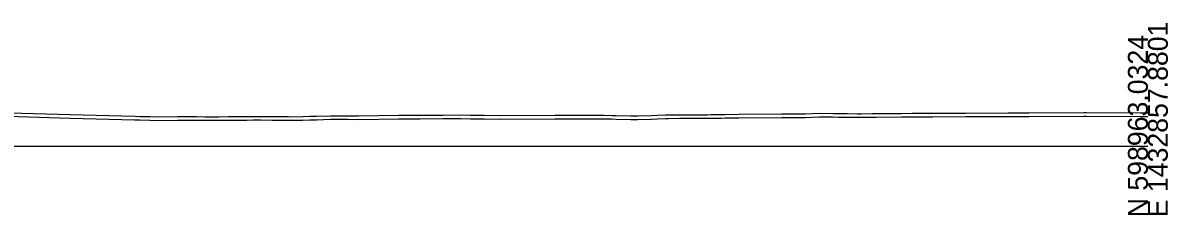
# Model space of a CAD drawing. Extents: x -26 to 2203, y -10 to 12201.
# Drawn here: x 442.1 to 602.8, y 9490.3 to 9517.3 of the extents above; entities that cross this region are included whole.
import ezdxf

# ---------------------------------------------------------------- set-up
doc = ezdxf.new("R2010")
doc.units = 0
for name, color, linetype in [('DESIGN - SHEET - Light Grid', 7, 'Continuous'), ('SURVEY - GROUND - Bottom of Topsoil Layer', 7, 'Continuous'), ('SURVEY - GROUND - Top of Ground', 7, 'Continuous')]:
    doc.layers.add(name, color=color, linetype=linetype)

msp = doc.modelspace()

# ---------------------------------------------------------------- linework, layer by layer
at = {"layer": 'DESIGN - SHEET - Light Grid'}
msp.add_line((300, 9500), (600, 9500), dxfattribs=at)
at = {"layer": 'SURVEY - GROUND - Bottom of Topsoil Layer'}
for p, q in [((436.02, 9504.31), (448.73, 9503.94)), ((448.73, 9503.94), (457.81, 9503.69)), ((457.81, 9503.69), (458.48, 9503.67)), ((458.48, 9503.67), (459.88, 9503.64)), ((459.88, 9503.64), (461.13, 9503.61)), ((461.13, 9503.61), (463.78, 9503.66)), ((463.78, 9503.66), (465.65, 9503.65)), ((465.65, 9503.65), (466.43, 9503.65)), ((466.43, 9503.65), (467.61, 9503.63)), ((467.61, 9503.63), (469.08, 9503.63)), ((469.08, 9503.63), (469.57, 9503.63)), ((469.57, 9503.63), (470.96, 9503.64)), ((470.96, 9503.64), (471.73, 9503.64)), ((471.73, 9503.64), (473.49, 9503.65)), ((473.49, 9503.65), (474.39, 9503.67)), ((474.39, 9503.67), (475.45, 9503.67)), ((475.45, 9503.67), (477.04, 9503.65)), ((477.04, 9503.65), (477.41, 9503.65)), ((477.41, 9503.65), (478.49, 9503.64)), ((478.49, 9503.64), (479.37, 9503.64)), ((479.37, 9503.64), (479.69, 9503.63)), ((479.69, 9503.63), (481.34, 9503.66)), ((481.34, 9503.66), (482.34, 9503.7)), ((482.34, 9503.7), (483.3, 9503.71)), ((483.3, 9503.71), (485.26, 9503.76)), ((485.26, 9503.76), (486.02, 9503.77)), ((486.02, 9503.77), (487.22, 9503.76)), ((487.22, 9503.76), (487.64, 9503.77)), ((487.64, 9503.77), (489.18, 9503.75)), ((489.18, 9503.75), (494.86, 9503.84)), ((494.86, 9503.84), (495.59, 9503.83)), ((495.59, 9503.83), (496.17, 9503.83)), ((496.17, 9503.83), (497.85, 9503.82)), ((497.85, 9503.82), (501.07, 9503.86)), ((501.07, 9503.86), (503.54, 9503.87)), ((503.54, 9503.87), (504.89, 9503.85)), ((504.89, 9503.85), (506.19, 9503.83)), ((506.19, 9503.83), (506.82, 9503.82)), ((506.82, 9503.82), (508.98, 9503.78)), ((508.98, 9503.78), (516.8, 9503.82)), ((516.8, 9503.82), (520.54, 9503.83)), ((520.54, 9503.83), (522.1, 9503.84)), ((522.1, 9503.84), (523.65, 9503.82)), ((523.65, 9503.82), (524.75, 9503.81)), ((524.75, 9503.81), (525.35, 9503.79)), ((525.35, 9503.79), (527.4, 9503.73)), ((527.4, 9503.73), (528.38, 9503.75)), ((528.38, 9503.75), (530.34, 9503.8)), ((530.34, 9503.8), (531.17, 9503.83)), ((531.17, 9503.83), (532.3, 9503.87)), ((532.3, 9503.87), (532.7, 9503.89)), ((532.7, 9503.89), (534.26, 9503.9)), ((534.26, 9503.9), (535.35, 9503.91)), ((535.35, 9503.91), (536.22, 9503.91)), ((536.22, 9503.91), (538.18, 9503.91)), ((538.18, 9503.91), (538.7, 9503.92)), ((538.7, 9503.92), (540.14, 9503.94)), ((540.14, 9503.94), (540.65, 9503.95)), ((540.65, 9503.95), (542.58, 9503.96)), ((542.58, 9503.96), (548.6, 9504.02)), ((548.6, 9504.02), (551.91, 9504.03)), ((551.91, 9504.03), (553.91, 9504.11)), ((553.91, 9504.11), (555.83, 9504.09)), ((555.83, 9504.09), (556.56, 9504.08)), ((556.56, 9504.08), (557.79, 9504.07)), ((557.79, 9504.07), (559.21, 9504.04)), ((559.21, 9504.04), (559.75, 9504.04)), ((559.75, 9504.04), (561.28, 9504.06)), ((561.28, 9504.06), (561.86, 9504.07)), ((561.86, 9504.07), (565.43, 9504.09)), ((565.43, 9504.09), (566.86, 9504.11)), ((566.86, 9504.11), (569.81, 9504.13)), ((569.81, 9504.13), (574.45, 9504.14)), ((574.45, 9504.14), (580.41, 9504.16)), ((580.41, 9504.16), (583.27, 9504.16)), ((583.27, 9504.16), (591.01, 9504.22)), ((591.01, 9504.22), (591.39, 9504.22)), ((591.39, 9504.22), (598.95, 9504.15)), ((598.95, 9504.15), (600, 9504.16))]:
    msp.add_line(p, q, dxfattribs=at)
at = {"layer": 'SURVEY - GROUND - Top of Ground'}
for p, q in [((436.02, 9504.81), (448.73, 9504.44)), ((448.73, 9504.44), (457.81, 9504.19)), ((497.85, 9504.32), (501.07, 9504.36)), ((501.07, 9504.36), (503.54, 9504.37)), ((503.54, 9504.37), (504.89, 9504.35)), ((504.89, 9504.35), (506.19, 9504.33)), ((531.17, 9504.33), (532.3, 9504.37)), ((532.3, 9504.37), (532.7, 9504.39)), ((532.7, 9504.39), (534.26, 9504.4)), ((534.26, 9504.4), (535.35, 9504.41)), ((535.35, 9504.41), (536.22, 9504.41)), ((536.22, 9504.41), (538.18, 9504.41)), ((538.18, 9504.41), (538.7, 9504.42)), ((538.7, 9504.42), (540.14, 9504.44)), ((540.14, 9504.44), (540.65, 9504.45)), ((540.65, 9504.45), (542.58, 9504.46)), ((542.58, 9504.46), (548.6, 9504.52)), ((548.6, 9504.52), (551.91, 9504.53)), ((551.91, 9504.53), (553.91, 9504.61)), ((553.91, 9504.61), (555.83, 9504.59)), ((555.83, 9504.59), (556.56, 9504.58)), ((556.56, 9504.58), (557.79, 9504.57)), ((557.79, 9504.57), (559.21, 9504.54)), ((559.21, 9504.54), (559.75, 9504.54)), ((559.75, 9504.54), (561.28, 9504.56)), ((561.28, 9504.56), (561.86, 9504.57)), ((561.86, 9504.57), (565.43, 9504.59)), ((565.43, 9504.59), (566.86, 9504.61)), ((566.86, 9504.61), (569.81, 9504.63)), ((569.81, 9504.63), (574.45, 9504.64)), ((574.45, 9504.64), (580.41, 9504.66)), ((580.41, 9504.66), (583.27, 9504.66)), ((583.27, 9504.66), (591.01, 9504.72)), ((591.01, 9504.72), (591.39, 9504.72)), ((591.39, 9504.72), (598.95, 9504.65)), ((598.95, 9504.65), (600, 9504.66)), ((457.81, 9504.19), (458.48, 9504.17)), ((458.48, 9504.17), (459.88, 9504.14)), ((459.88, 9504.14), (461.13, 9504.11)), ((461.13, 9504.11), (463.78, 9504.16)), ((463.78, 9504.16), (465.65, 9504.15)), ((465.65, 9504.15), (466.43, 9504.15)), ((466.43, 9504.15), (467.61, 9504.13)), ((467.61, 9504.13), (469.08, 9504.13)), ((469.08, 9504.13), (469.57, 9504.13)), ((469.57, 9504.13), (470.96, 9504.14)), ((470.96, 9504.14), (471.73, 9504.14)), ((471.73, 9504.14), (473.49, 9504.15)), ((473.49, 9504.15), (474.39, 9504.17)), ((474.39, 9504.17), (475.45, 9504.17)), ((475.45, 9504.17), (477.04, 9504.15)), ((477.04, 9504.15), (477.41, 9504.15)), ((477.41, 9504.15), (478.49, 9504.14)), ((478.49, 9504.14), (479.37, 9504.14)), ((479.37, 9504.14), (479.69, 9504.13)), ((479.69, 9504.13), (481.34, 9504.16)), ((481.34, 9504.16), (482.34, 9504.2)), ((482.34, 9504.2), (483.3, 9504.21)), ((483.3, 9504.21), (485.26, 9504.26)), ((485.26, 9504.26), (486.02, 9504.27)), ((486.02, 9504.27), (487.22, 9504.26)), ((487.22, 9504.26), (487.64, 9504.27)), ((487.64, 9504.27), (489.18, 9504.25)), ((489.18, 9504.25), (494.86, 9504.34)), ((494.86, 9504.34), (495.59, 9504.33)), ((495.59, 9504.33), (496.17, 9504.33)), ((496.17, 9504.33), (497.85, 9504.32)), ((506.19, 9504.33), (506.82, 9504.32)), ((506.82, 9504.32), (508.98, 9504.28)), ((508.98, 9504.28), (516.8, 9504.32)), ((516.8, 9504.32), (520.54, 9504.33)), ((520.54, 9504.33), (522.1, 9504.34)), ((522.1, 9504.34), (523.65, 9504.32)), ((523.65, 9504.32), (524.75, 9504.31)), ((524.75, 9504.31), (525.35, 9504.29)), ((525.35, 9504.29), (527.4, 9504.23)), ((527.4, 9504.23), (528.38, 9504.25)), ((528.38, 9504.25), (530.34, 9504.3)), ((530.34, 9504.3), (531.17, 9504.33))]:
    msp.add_line(p, q, dxfattribs=at)

# ---------------------------------------------------------------- texts
at = {"layer": 'DESIGN - SHEET - Light Grid'}
for s, p in [('E 1432857.8801', (602.8, 9490)), ('N 598963.0324', (600, 9490))]:
    msp.add_text(s, height=2.8, rotation=90, dxfattribs=at).set_placement(p)

doc.saveas('drawing.dxf')
